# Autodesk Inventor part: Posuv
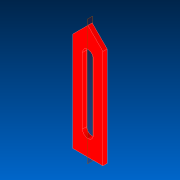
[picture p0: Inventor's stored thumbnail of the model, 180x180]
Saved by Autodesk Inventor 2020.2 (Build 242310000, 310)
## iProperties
Created: 2021-01
Part Number: Posuv
Material: Všeobecné
Document SubType Name: Modeling
Designer: Pavel
Density: 1 g/cm^3
Appearance: Výchozí
UlozenoKym: navara
LastSaveDate: 12.01.2021
Author: Pavel
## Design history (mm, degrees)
sketch "Náčrt1"
  geometry: L1 (0, 0)-(14, 0); L2 (14, 0)-(14, 46); L3 (0, 46)-(0, 0); L4 (7, 40.833)-(7, 10); L5 (4.5, 40.833)-(4.5, 10); L6 (9.5, 10)-(9.5, 40.833); L7 (7, 53)-(0, 46); L8 (7, 53)-(14, 46); A1 r 2.5 centre (7, 40.833) between (9.5, 40.833) and (4.5, 40.833); A2 r 2.5 centre (7, 10) between (4.5, 10) and (9.5, 10); 1 further point
  constraints: 18 end point, 4 point on circle, 4 tangent, 2 centre point, 2 parallel, 1 horizontal, 1 midpoint, 1 perpendicular, 1 vertical
  dimensions: "d1" = 5 diameter of A2; "d2" = 45 deg angle of L7 L3; "d3" = 45 deg angle of L2 L8
extrude "Vysunutí1" new body sketch "Náčrt1" distance "d4" = 2; taper "d5" = 0 deg
node "Pracovní rovina1"
node "Pracovní rovina2"
node "Těleso1"
